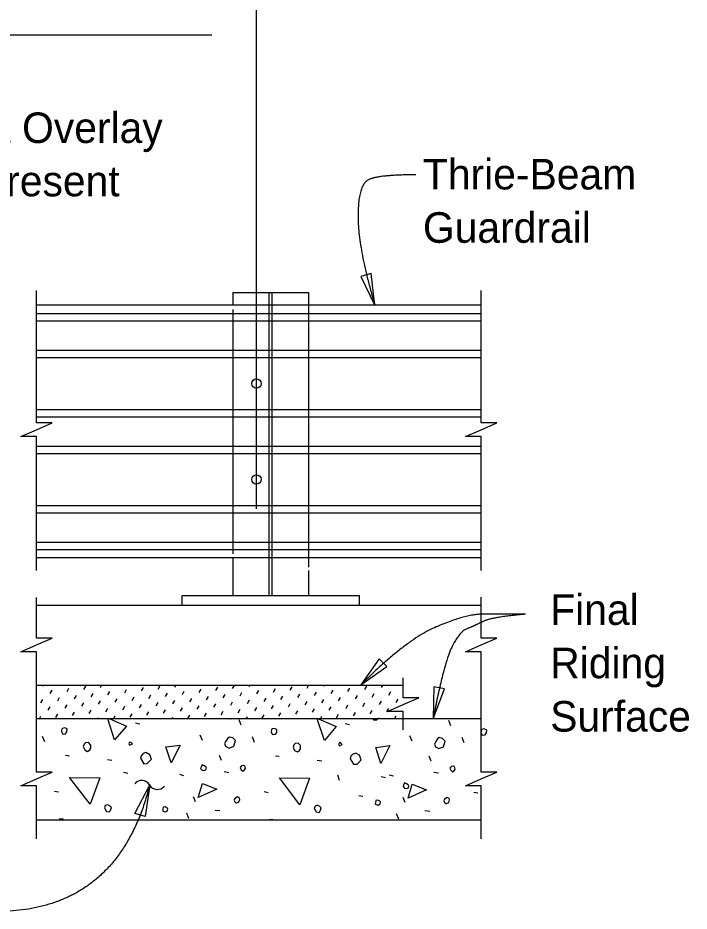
# Model space of a CAD drawing. Extents: x 21516.9 to 21589, y 56155.1 to 56195.
# Drawn here: x 21532 to 21536.43, y 56169.63 to 56175.53 of the extents above; entities that cross this region are included whole.
import ezdxf

# ---------------------------------------------------------------- set-up
doc = ezdxf.new("R2010")
doc.units = 0
for name, color, linetype in [('AdhocPoint_dp', 7, 'Continuous'), ('Border', 7, 'Continuous'), ('Patterning', 7, 'Continuous'), ('PlotBorder_dp', 7, 'Continuous'), ('TextMisc', 7, 'Continuous')]:
    doc.layers.add(name, color=color, linetype=linetype)

msp = doc.modelspace()

# ---------------------------------------------------------------- linework, layer by layer
at = {"layer": 'AdhocPoint_dp'}
for p, q in [((21532.1195, 56171.6541), (21535.0551, 56171.6541)), ((21534.5408, 56171.1231), (21532.1195, 56171.1231)), ((21535.0551, 56170.9041), (21532.1195, 56170.9041)), ((21532.1195, 56170.2374), (21535.0551, 56170.2374))]:
    msp.add_line(p, q, dxfattribs=at)
at = {"layer": 'Border'}
for p, q in [((21533.6554, 56171.7167), (21533.6554, 56173.7167)), ((21533.6763, 56171.7167), (21533.6763, 56173.7167)), ((21533.9158, 56173.7167), (21533.9158, 56171.9037)), ((21533.4158, 56173.6048), (21533.4158, 56171.9929))]:
    msp.add_line(p, q, dxfattribs=at)
at = {"layer": 'Patterning'}
for p, q in [((21533.4158, 56173.7167), (21533.9158, 56173.7167)), ((21533.4158, 56173.7167), (21533.4158, 56173.6334)), ((21535.0551, 56173.6333), (21532.1195, 56173.6333)), ((21535.0551, 56171.9666), (21532.1195, 56171.9666)), ((21533.4158, 56171.9667), (21533.4158, 56171.7167)), ((21533.9158, 56171.8834), (21533.9158, 56171.7167)), ((21533.0825, 56171.7167), (21534.2492, 56171.7167)), ((21533.0825, 56171.6542), (21533.0825, 56171.7167)), ((21533.4158, 56171.7167), (21533.9158, 56171.7167)), ((21534.2492, 56171.7167), (21534.2492, 56171.6542)), ((21533.0825, 56171.6542), (21534.2492, 56171.6542))]:
    msp.add_line(p, q, dxfattribs=at)
for centre in [(21533.5721, 56173.1166), (21533.5721, 56172.4835)]:
    msp.add_circle(centre, 0.0312, dxfattribs=at)
at = {"layer": 'PlotBorder_dp'}
for p, q in [((21533.5721, 56172.2893), (21533.5721, 56186.7281)), ((21533.2773, 56175.4166), (21527.7324, 56175.4166))]:
    msp.add_line(p, q, dxfattribs=at)
for points in [[(21534.3539, 56173.6325), (21534.3288, 56173.8422), (21534.2611, 56173.8223)], [(21534.2605, 56171.1272), (21534.4327, 56171.2495), (21534.3828, 56171.2994)], [(21534.7378, 56170.9036), (21534.8126, 56171.1012), (21534.7433, 56171.1148)], [(21532.8674, 56170.4673), (21532.8369, 56170.2583), (21532.7698, 56170.28)]]:
    msp.add_lwpolyline(points, close=True, dxfattribs=at)
for points in [[(21532.1195, 56171.8836), (21532.1195, 56172.7668), (21532.0162, 56172.7668), (21532.1195, 56172.8118), (21532.2228, 56172.8568), (21532.1195, 56172.8568), (21532.1195, 56173.7298)], [(21535.0551, 56171.8836), (21535.0551, 56172.7668), (21534.9518, 56172.7668), (21535.0551, 56172.8118), (21535.1584, 56172.8568), (21535.0551, 56172.8568), (21535.0551, 56173.7298)], [(21532.1195, 56170.8762), (21532.1195, 56171.3462), (21532.0162, 56171.3462), (21532.1195, 56171.3912), (21532.2228, 56171.4362), (21532.1195, 56171.4362), (21532.1195, 56171.7042)], [(21535.0551, 56170.8762), (21535.0551, 56171.3462), (21534.9518, 56171.3462), (21535.0551, 56171.3912), (21535.1584, 56171.4362), (21535.0551, 56171.4362), (21535.0551, 56171.7071)], [(21534.5409, 56170.8322), (21534.5409, 56170.9531), (21534.4375, 56170.9531), (21534.5409, 56170.9981), (21534.6442, 56171.0431), (21534.5409, 56171.0431), (21534.5409, 56171.1736)], [(21532.1195, 56170.1111), (21532.1195, 56170.4617), (21532.0162, 56170.4617), (21532.1195, 56170.5067), (21532.2228, 56170.5517), (21532.1195, 56170.5517), (21532.1195, 56170.8762)], [(21535.0551, 56170.1111), (21535.0551, 56170.4617), (21534.9518, 56170.4617), (21535.0551, 56170.5067), (21535.1584, 56170.5517), (21535.0551, 56170.5517), (21535.0551, 56170.8762)]]:
    msp.add_lwpolyline(points, dxfattribs=at)
for centre, start, end in [((21532.815, 56170.4377), 30.00813, 141.73535), ((21532.9182, 56170.4973), 210.00813, 321.73535)]:
    msp.add_arc(centre, 0.0596, start, end, dxfattribs=at)
for points in [[(21534.6242, 56174.4941), (21534.3839, 56174.4941), (21534.2426, 56174.4304), (21534.2426, 56174.0098), (21534.3539, 56173.6325)], [(21535.3489, 56171.5938), (21535.158, 56171.5938), (21534.9531, 56171.5938), (21534.5573, 56171.4241), (21534.2605, 56171.1272)], [(21535.3489, 56171.5938), (21535.123, 56171.5754), (21534.9993, 56171.5117), (21534.9163, 56171.4817), (21534.812, 56171.2819), (21534.7378, 56170.9036)], [(21532.8674, 56170.4673), (21532.6689, 56169.6813), (21531.9422, 56169.6346)]]:
    msp.add_open_spline(points, degree=2, dxfattribs=at)
at = {"layer": 'TextMisc'}
for p, q in [((21532.1195, 56173.5778), (21535.0551, 56173.5778)), ((21532.1195, 56173.5295), (21535.0551, 56173.5295)), ((21532.1195, 56173.3367), (21535.0551, 56173.3367)), ((21532.1195, 56173.2885), (21535.0551, 56173.2885)), ((21532.1195, 56172.9445), (21535.0551, 56172.9445)), ((21532.1195, 56172.8963), (21535.0551, 56172.8963)), ((21532.1195, 56172.7035), (21535.0551, 56172.7035)), ((21532.1195, 56172.6554), (21535.0551, 56172.6554)), ((21532.1195, 56172.3114), (21535.0551, 56172.3114)), ((21532.1195, 56172.2632), (21535.0551, 56172.2632)), ((21532.1195, 56172.0704), (21535.0551, 56172.0704)), ((21532.1195, 56172.0221), (21535.0551, 56172.0221)), ((21532.162, 56171.1203), (21532.1636, 56171.1231)), ((21532.2108, 56171.0715), (21532.2238, 56171.0939)), ((21532.3215, 56171.0845), (21532.3344, 56171.1068)), ((21532.4321, 56171.0974), (21532.4451, 56171.1198)), ((21532.5427, 56171.1104), (21532.5501, 56171.1231)), ((21532.5916, 56171.0615), (21532.6045, 56171.0839)), ((21532.7022, 56171.0745), (21532.7152, 56171.0969)), ((21532.8128, 56171.0875), (21532.8258, 56171.1099)), ((21532.9235, 56171.1004), (21532.9364, 56171.1228)), ((21533.0341, 56171.1134), (21533.0397, 56171.1231)), ((21533.0829, 56171.0646), (21533.0959, 56171.087)), ((21533.1936, 56171.0775), (21533.2065, 56171.0999)), ((21533.3042, 56171.0905), (21533.3172, 56171.1129)), ((21533.4148, 56171.1035), (21533.4262, 56171.1231)), ((21533.4637, 56171.0546), (21533.4766, 56171.077)), ((21533.5255, 56171.1164), (21533.5293, 56171.1231)), ((21533.5743, 56171.0676), (21533.5873, 56171.09)), ((21533.6849, 56171.0805), (21533.6979, 56171.1029)), ((21533.7956, 56171.0935), (21533.8085, 56171.1159)), ((21533.9062, 56171.1065), (21533.9158, 56171.1231)), ((21533.955, 56171.0576), (21533.968, 56171.08)), ((21534.0168, 56171.1194), (21534.0189, 56171.1231)), ((21534.0657, 56171.0706), (21534.0786, 56171.093)), ((21534.1763, 56171.0836), (21534.1893, 56171.106)), ((21534.2869, 56171.0965), (21534.2999, 56171.1189)), ((21534.3976, 56171.1095), (21534.4054, 56171.1231)), ((21534.4464, 56171.0607), (21534.4594, 56171.0831)), ((21534.5082, 56171.1225), (21534.5086, 56171.1231)), ((21532.149, 56171.0097), (21532.162, 56171.0321)), ((21532.2597, 56171.0227), (21532.2726, 56171.045)), ((21532.3703, 56171.0356), (21532.3833, 56171.058)), ((21532.4809, 56171.0486), (21532.4939, 56171.071)), ((21532.5298, 56170.9997), (21532.5427, 56171.0221)), ((21532.6404, 56171.0127), (21532.6534, 56171.0351)), ((21532.751, 56171.0257), (21532.764, 56171.0481)), ((21532.8617, 56171.0386), (21532.8746, 56171.061)), ((21532.9723, 56171.0516), (21532.9853, 56171.074)), ((21533.0211, 56171.0028), (21533.0341, 56171.0252)), ((21533.1318, 56171.0157), (21533.1447, 56171.0381)), ((21533.2424, 56171.0287), (21533.2554, 56171.0511)), ((21533.353, 56171.0417), (21533.366, 56171.0641)), ((21533.5125, 56171.0058), (21533.5255, 56171.0282)), ((21533.6231, 56171.0188), (21533.6361, 56171.0411)), ((21533.7338, 56171.0317), (21533.7467, 56171.0541)), ((21533.8444, 56171.0447), (21533.8574, 56171.0671)), ((21533.8932, 56170.9958), (21533.9062, 56171.0182)), ((21534.0039, 56171.0088), (21534.0168, 56171.0312)), ((21534.1145, 56171.0218), (21534.1275, 56171.0442)), ((21534.2251, 56171.0347), (21534.2381, 56171.0571)), ((21534.3358, 56171.0477), (21534.3487, 56171.0701)), ((21534.3846, 56170.9989), (21534.3976, 56171.0213)), ((21534.4952, 56171.0118), (21534.5082, 56171.0342)), ((21532.1979, 56170.9609), (21532.2108, 56170.9832)), ((21532.3085, 56170.9738), (21532.3215, 56170.9962)), ((21532.4191, 56170.9868), (21532.4321, 56171.0092)), ((21532.468, 56170.9379), (21532.4809, 56170.9603)), ((21532.5786, 56170.9509), (21532.5916, 56170.9733)), ((21532.6892, 56170.9639), (21532.7022, 56170.9863)), ((21532.7999, 56170.9768), (21532.8128, 56170.9992)), ((21532.9105, 56170.9898), (21532.9235, 56171.0122)), ((21532.9593, 56170.941), (21532.9723, 56170.9634)), ((21533.07, 56170.9539), (21533.0829, 56170.9763)), ((21533.1806, 56170.9669), (21533.1936, 56170.9893)), ((21533.2912, 56170.9799), (21533.3042, 56171.0023)), ((21533.4019, 56170.9928), (21533.4148, 56171.0152)), ((21533.4507, 56170.944), (21533.4637, 56170.9664)), ((21533.5613, 56170.957), (21533.5743, 56170.9793)), ((21533.672, 56170.9699), (21533.6849, 56170.9923)), ((21533.7826, 56170.9829), (21533.7956, 56171.0053)), ((21533.9421, 56170.947), (21533.955, 56170.9694)), ((21534.0527, 56170.96), (21534.0657, 56170.9824)), ((21534.1633, 56170.9729), (21534.1763, 56170.9953)), ((21534.274, 56170.9859), (21534.2869, 56171.0083)), ((21534.3228, 56170.9371), (21534.3358, 56170.9595)), ((21534.4334, 56170.95), (21534.4464, 56170.9724)), ((21532.139, 56170.9041), (21532.149, 56170.9215)), ((21532.2467, 56170.912), (21532.2597, 56170.9344)), ((21532.3573, 56170.925), (21532.3703, 56170.9474)), ((21532.5255, 56170.9042), (21532.5298, 56170.9115)), ((21532.6287, 56170.9042), (21532.6404, 56170.9245)), ((21532.7381, 56170.915), (21532.751, 56170.9374)), ((21532.8487, 56170.928), (21532.8617, 56170.9504)), ((21533.0152, 56170.9042), (21533.0211, 56170.9145)), ((21533.1188, 56170.9051), (21533.1318, 56170.9275)), ((21533.2294, 56170.9181), (21533.2424, 56170.9405)), ((21533.3401, 56170.931), (21533.353, 56170.9534)), ((21533.4017, 56170.9043), (21533.4019, 56170.9046)), ((21533.5048, 56170.9043), (21533.5125, 56170.9175)), ((21533.6102, 56170.9081), (21533.6231, 56170.9305)), ((21533.7208, 56170.9211), (21533.7338, 56170.9435)), ((21533.8314, 56170.934), (21533.8444, 56170.9564)), ((21533.8913, 56170.9043), (21533.8932, 56170.9076)), ((21533.9945, 56170.9043), (21534.0039, 56170.9206)), ((21534.1015, 56170.9111), (21534.1145, 56170.9335)), ((21534.2122, 56170.9241), (21534.2251, 56170.9465)), ((21534.381, 56170.9044), (21534.3846, 56170.9106)), ((21534.4841, 56170.9044), (21534.4952, 56170.9236)), ((21532.7731, 56170.877), (21532.8014, 56170.8699)), ((21533.4713, 56170.861), (21533.4572, 56170.8964)), ((21534.1578, 56170.8734), (21534.186, 56170.8664)), ((21534.856, 56170.8575), (21534.8419, 56170.8929)), ((21532.1744, 56170.7521), (21532.1603, 56170.7874)), ((21533.215, 56170.7603), (21533.2009, 56170.7956)), ((21533.5591, 56170.7485), (21533.545, 56170.7839)), ((21534.5997, 56170.7567), (21534.5856, 56170.7921)), ((21534.9438, 56170.745), (21534.9296, 56170.7804)), ((21532.3123, 56170.6637), (21532.3371, 56170.6601)), ((21532.5881, 56170.6354), (21532.6181, 56170.6301)), ((21533.3405, 56170.6277), (21533.3282, 56170.6613)), ((21533.697, 56170.6601), (21533.7217, 56170.6566)), ((21533.9728, 56170.6319), (21534.0028, 56170.6266)), ((21534.7252, 56170.6242), (21534.7128, 56170.6578)), ((21532.695, 56170.5515), (21532.7233, 56170.5444)), ((21533.3594, 56170.5559), (21533.3894, 56170.5505)), ((21534.744, 56170.5523), (21534.7741, 56170.547)), ((21533.063, 56170.5375), (21533.0913, 56170.5305)), ((21534.1213, 56170.4975), (21534.1089, 56170.5311)), ((21534.3953, 56170.524), (21534.4235, 56170.517)), ((21534.4477, 56170.534), (21534.476, 56170.5269)), ((21532.2381, 56170.4268), (21532.2646, 56170.4215)), ((21533.1691, 56170.355), (21533.1567, 56170.3885)), ((21533.6227, 56170.4233), (21533.6493, 56170.418)), ((21534.2485, 56170.3985), (21534.2751, 56170.3932)), ((21534.5537, 56170.3514), (21534.5414, 56170.385)), ((21535.0074, 56170.4197), (21535.0339, 56170.4144)), ((21533.1266, 56170.2453), (21533.1125, 56170.2807)), ((21533.2992, 56170.3013), (21533.3311, 56170.2978)), ((21534.5113, 56170.2418), (21534.4972, 56170.2772)), ((21534.6839, 56170.2978), (21534.7157, 56170.2942))]:
    msp.add_line(p, q, dxfattribs=at)
for points in [[(21532.6358, 56170.7644), (21532.5904, 56170.9041)], [(21532.6043, 56170.9041), (21532.7136, 56170.8564), (21532.6358, 56170.7644)], [(21534.0205, 56170.7609), (21533.9739, 56170.9041)], [(21533.9808, 56170.9041), (21534.0983, 56170.8528), (21534.0205, 56170.7609)], [(21534.3426, 56170.9041), (21534.3451, 56170.8982), (21534.3416, 56170.9017)], [(21534.3451, 56170.8982), (21534.3664, 56170.8982), (21534.3723, 56170.9041)], [(21532.284, 56170.8192), (21532.2929, 56170.8033), (21532.3123, 56170.8051), (21532.3212, 56170.8175), (21532.3229, 56170.8369), (21532.3105, 56170.8422), (21532.3017, 56170.844), (21532.2911, 56170.8405), (21532.2876, 56170.8369), (21532.284, 56170.8192)], [(21533.3688, 56170.7232), (21533.3918, 56170.7108), (21533.4218, 56170.7232), (21533.4342, 56170.7603), (21533.4165, 56170.778), (21533.3936, 56170.7833), (21533.383, 56170.7762), (21533.3706, 56170.7567), (21533.3617, 56170.7408), (21533.3688, 56170.7232)], [(21533.6687, 56170.8157), (21533.6775, 56170.7998), (21533.697, 56170.8016), (21533.7058, 56170.8139), (21533.7076, 56170.8334), (21533.6952, 56170.8387), (21533.6864, 56170.8405), (21533.6758, 56170.8369), (21533.6722, 56170.8334), (21533.6687, 56170.8157)], [(21535.0534, 56170.8122), (21535.0622, 56170.7963), (21535.0817, 56170.798), (21535.0905, 56170.8104), (21535.0923, 56170.8299), (21535.0799, 56170.8352), (21535.0711, 56170.8369), (21535.0605, 56170.8334), (21535.0569, 56170.8299), (21535.0534, 56170.8122)], [(21532.429, 56170.7203), (21532.4396, 56170.699), (21532.4573, 56170.6884), (21532.4714, 56170.699), (21532.4785, 56170.7096), (21532.4785, 56170.7309), (21532.4626, 56170.7468), (21532.4431, 56170.745), (21532.4343, 56170.7362), (21532.429, 56170.7203)], [(21532.7348, 56170.7291), (21532.7543, 56170.7379), (21532.7472, 56170.745), (21532.7348, 56170.7503), (21532.7295, 56170.7379), (21532.7348, 56170.7291)], [(21533.0082, 56170.6136), (21532.9746, 56170.7179), (21533.0683, 56170.7302), (21533.0082, 56170.6136)], [(21533.8137, 56170.7167), (21533.8243, 56170.6955), (21533.842, 56170.6849), (21533.8561, 56170.6955), (21533.8632, 56170.7061), (21533.8632, 56170.7273), (21533.8473, 56170.7432), (21533.8278, 56170.7415), (21533.819, 56170.7326), (21533.8137, 56170.7167)], [(21534.1195, 56170.7256), (21534.1389, 56170.7344), (21534.1319, 56170.7415), (21534.1195, 56170.7468), (21534.1142, 56170.7344), (21534.1195, 56170.7256)], [(21534.3929, 56170.61), (21534.3593, 56170.7143), (21534.453, 56170.7267), (21534.3929, 56170.61)], [(21534.7535, 56170.7196), (21534.7765, 56170.7073), (21534.8065, 56170.7196), (21534.8189, 56170.7567), (21534.8012, 56170.7744), (21534.7782, 56170.7797), (21534.7676, 56170.7727), (21534.7553, 56170.7532), (21534.7464, 56170.7373), (21534.7535, 56170.7196)], [(21532.8055, 56170.6442), (21532.8285, 56170.6071), (21532.8515, 56170.6089), (21532.8603, 56170.6177), (21532.8798, 56170.6372), (21532.8674, 56170.6672), (21532.8426, 56170.6814), (21532.825, 56170.6743), (21532.8108, 56170.6601), (21532.8055, 56170.6442)], [(21534.1902, 56170.6407), (21534.2132, 56170.6036), (21534.2362, 56170.6053), (21534.245, 56170.6142), (21534.2644, 56170.6336), (21534.2521, 56170.6637), (21534.2273, 56170.6778), (21534.2096, 56170.6708), (21534.1955, 56170.6566), (21534.1902, 56170.6407)], [(21533.2139, 56170.5646), (21533.2263, 56170.5628), (21533.2387, 56170.5681), (21533.2422, 56170.5787), (21533.2369, 56170.5876), (21533.2263, 56170.5946), (21533.2139, 56170.5999), (21533.2069, 56170.5858), (21533.2033, 56170.5752), (21533.2139, 56170.5646)], [(21533.4707, 56170.5682), (21533.4813, 56170.5576), (21533.4919, 56170.5647), (21533.499, 56170.5753), (21533.4955, 56170.593), (21533.4866, 56170.5947), (21533.4743, 56170.593), (21533.4636, 56170.5824), (21533.4707, 56170.5682)], [(21534.8554, 56170.5647), (21534.866, 56170.5541), (21534.8766, 56170.5612), (21534.8837, 56170.5718), (21534.8801, 56170.5894), (21534.8713, 56170.5912), (21534.8589, 56170.5894), (21534.8483, 56170.5788), (21534.8554, 56170.5647)], [(21532.4732, 56170.3402), (21532.3388, 56170.517), (21532.5386, 56170.5152), (21532.4732, 56170.3402)], [(21533.8579, 56170.3366), (21533.7235, 56170.5134), (21533.9233, 56170.5117), (21533.8579, 56170.3366)], [(21533.1879, 56170.3844), (21533.2162, 56170.4763), (21533.3099, 56170.4392), (21533.1879, 56170.3844)], [(21534.5502, 56170.4456), (21534.5626, 56170.4439), (21534.5749, 56170.4492), (21534.5785, 56170.4598), (21534.5732, 56170.4686), (21534.5626, 56170.4757), (21534.5502, 56170.481), (21534.5431, 56170.4668), (21534.5396, 56170.4562), (21534.5502, 56170.4456)], [(21534.5726, 56170.3808), (21534.6008, 56170.4728), (21534.6945, 56170.4356), (21534.5726, 56170.3808)], [(21533.4354, 56170.349), (21533.4424, 56170.349), (21533.4566, 56170.3561), (21533.4619, 56170.372), (21533.4601, 56170.3808), (21533.446, 56170.3879), (21533.4283, 56170.3773), (21533.4248, 56170.3667), (21533.4283, 56170.3561), (21533.4354, 56170.349)], [(21534.82, 56170.3455), (21534.8271, 56170.3455), (21534.8413, 56170.3526), (21534.8466, 56170.3685), (21534.8448, 56170.3773), (21534.8306, 56170.3844), (21534.813, 56170.3738), (21534.8094, 56170.3632), (21534.813, 56170.3526), (21534.82, 56170.3455)], [(21532.5722, 56170.3084), (21532.581, 56170.2925), (21532.6022, 56170.2889), (21532.6111, 56170.3048), (21532.6146, 56170.319), (21532.6058, 56170.3278), (21532.5899, 56170.3366), (21532.5739, 56170.3313), (21532.5686, 56170.3154), (21532.5722, 56170.3084)], [(21532.953, 56170.2954), (21532.9725, 56170.2901), (21532.9849, 56170.2989), (21532.9866, 56170.3113), (21532.9831, 56170.3148), (21532.969, 56170.3219), (21532.9566, 56170.3201), (21532.9548, 56170.3078), (21532.953, 56170.2954)], [(21533.9569, 56170.3048), (21533.9657, 56170.2889), (21533.9869, 56170.2854), (21533.9957, 56170.3013), (21533.9993, 56170.3154), (21533.9904, 56170.3243), (21533.9745, 56170.3331), (21533.9586, 56170.3278), (21533.9533, 56170.3119), (21533.9569, 56170.3048)], [(21534.3564, 56170.3402), (21534.3758, 56170.3349), (21534.3882, 56170.3437), (21534.39, 56170.3561), (21534.3864, 56170.3596), (21534.3723, 56170.3667), (21534.3599, 56170.3649), (21534.3581, 56170.3526), (21534.3564, 56170.3402)], [(21532.2974, 56170.2374), (21532.2964, 56170.2412), (21532.2734, 56170.243), (21532.2716, 56170.2374)], [(21533.6811, 56170.2374), (21533.6811, 56170.2377), (21533.6581, 56170.2394), (21533.6574, 56170.2374)]]:
    msp.add_lwpolyline(points, dxfattribs=at)

# ---------------------------------------------------------------- texts
at = {"layer": 'PlotBorder_dp'}
for s, p in [('Asphalt Overlay', (21531.0506, 56174.7041)), ('when present', (21531.0506, 56174.3521)), ('Thrie-Beam ', (21534.671, 56174.3975)), ('Guardrail', (21534.671, 56174.0455)), ('Final ', (21535.5115, 56171.5235)), ('Riding ', (21535.5115, 56171.1715)), ('Surface', (21535.5115, 56170.8195))]:
    msp.add_text(s, height=0.2016, dxfattribs=at).set_placement(p)

doc.saveas('drawing.dxf')
